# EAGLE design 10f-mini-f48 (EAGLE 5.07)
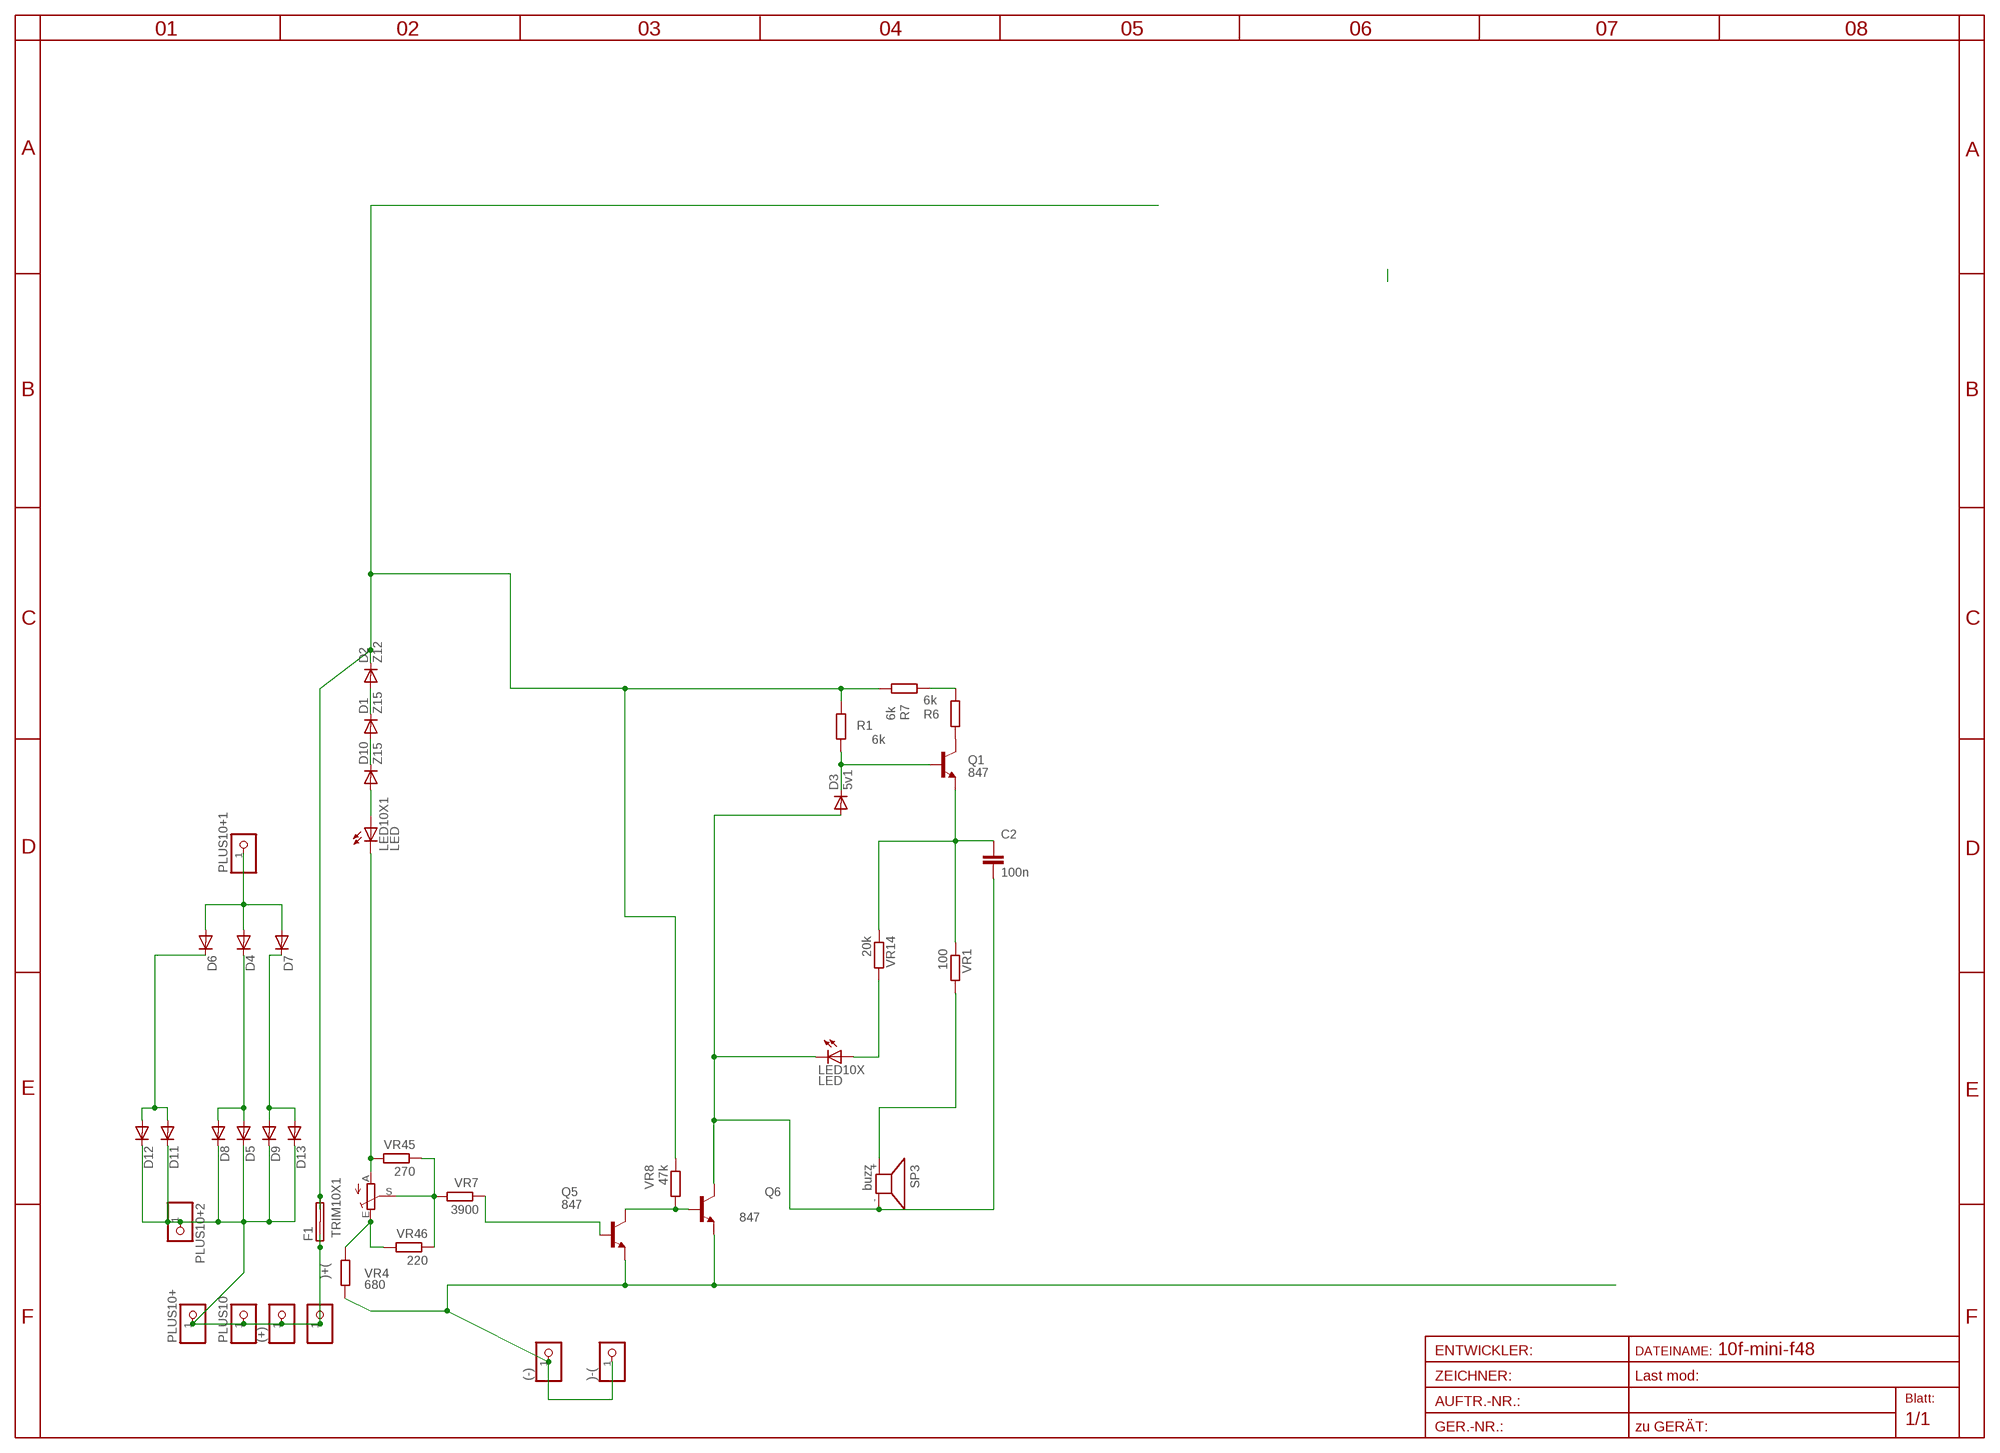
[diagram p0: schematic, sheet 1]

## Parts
(+)  PINHD-1X14.5MM  [1X4MM5]
(-)  PINHD-1X14.5MM  [1X4MM5]
)+(  PINHD-1X11X0.4  [1X01]
)-(  PINHD-1X11X0.4  [1X01]
C2  100n  C-EUC1206  [C1206]
D1  Z15  DIODE-MINIMELF  [MINIMELF]
D2  Z12  DIODE-MINIMELF  [MINIMELF]
D3  5v1  DIODE-MINIMELF  [MINIMELF]
D4  DIODE-SMC  [SMC]
D5  DIODE-SMC  [SMC]
D6  DIODE-SMC  [SMC]
D7  DIODE-SMC  [SMC]
D8  DIODE-SMC  [SMC]
D9  DIODE-SMC  [SMC]
D10  Z15  DIODE-MINIMELF  [MINIMELF]
D11  DIODE-SMC  [SMC]
D12  DIODE-SMC  [SMC]
D13  DIODE-SMC  [SMC]
F1  SHK20L7MM5  [7MM5]
LED10X  LED  LEDCHIPLED_1206  [CHIPLED_1206]
LED10X1  LED  LEDCHIPLED_1206  [CHIPLED_1206]
PLUS10  PINHD-1X14.5MM  [1X4MM5]
PLUS10+  PINHD-1X11X0.4  [1X01]
PLUS10+1  PINHD-1X11X0.4  [1X01]
PLUS10+2  PINHD-1X11X0.4  [1X01]
Q1  847  BC847CSMD  [SOT23]
Q5  847  BC847CSMD  [SOT23]
Q6  847  BC847CSMD  [SOT23]
R1  6k  R-EU_R1206  [R1206]
R6  6k  R-EU_R1206  [R1206]
R7  6k  R-EU_R1206  [R1206]
SP3  buzz  KSS12017MM  [KSS1202]
TRIM10X1  TRIM_EU-S64W  [S64W]
VR1  100  R-EU_R0805  [R0805]
VR4  680  R-EU_R0805  [R0805]
VR7  3900  R-EU_R1206  [R1206]
VR8  47k  R-EU_R1206  [R1206]
VR14  20k  R-EU_R0805  [R0805]
VR45  270  R-EU_R0805  [R0805]
VR46  220  R-EU_R1206  [R1206]

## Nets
BUZZ+: SP3.+ VR1.2
FPLUS: D2.C F1.2A F1.2B R1.2 R7.1 VR8.1
INPLUS: (+).1 )+(.1 D5.C D8.C D9.C D11.C D12.C D13.C F1.1A F1.1B PLUS10+2.1 PLUS10+.1 PLUS10.1
LEDA: LED10X.A VR14.2
N$1: D1.C D2.A
N$2: D3.C Q1.1(B) R1.1
N$3: Q5.3(C) Q6.1(B) VR8.2
N$4: D1.A D10.C
N$5: C2.2 D3.A LED10X.C Q6.3(C) SP3.-
N$6: Q1.3(C) R6.2
N$7: D4.C D5.A D8.A
N$8: C2.1 Q1.2(E) VR1.1 VR14.1
N$9: D4.A D6.A D7.A PLUS10+1.1
N$10: D10.A LED10X1.A
N$11: D7.C D9.A D13.A
N$12: D6.C D11.A D12.A
N$17: LED10X1.C TRIM10X1.A VR45.2
N$18: R6.1 R7.2
N$22: TRIM10X1.S VR7.2 VR45.1 VR46.1
N$24: TRIM10X1.E VR4.1 VR46.2
N$168: Q5.1(B) VR7.1
VSS: (-).1 )-(.1 Q5.2(E) Q6.2(E) VR4.2

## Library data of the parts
(+) (-) )+( )-( PLUS10 PLUS10+ PLUS10+1 PLUS10+2 = pinhead:PINHD-1X1: PIN HEADER
C2 = rcl:C-EU: CAPACITOR, European symbol
D1-D13 = diode:DIODE-: DIODE
F1 = fuse:SHK20L: FUSE HOLDER 5 x 20 mm, SH contact, SHH1 Schukat, E1073 Buerklin
LED10X LED10X1 = led:LED: LED
Q1 Q5 Q6 = transistor-npn:BC847*: NPN Transistor
R1 R6 R7 VR1 VR4 VR7 VR8 VR14 VR45 VR46 = rcl-2:R-EU_: RESISTOR, European symbol
SP3 = buzzer:KSS1201: SPEAKER
TRIM10X1 = pot:TRIM_EU-: POTENTIOMETER

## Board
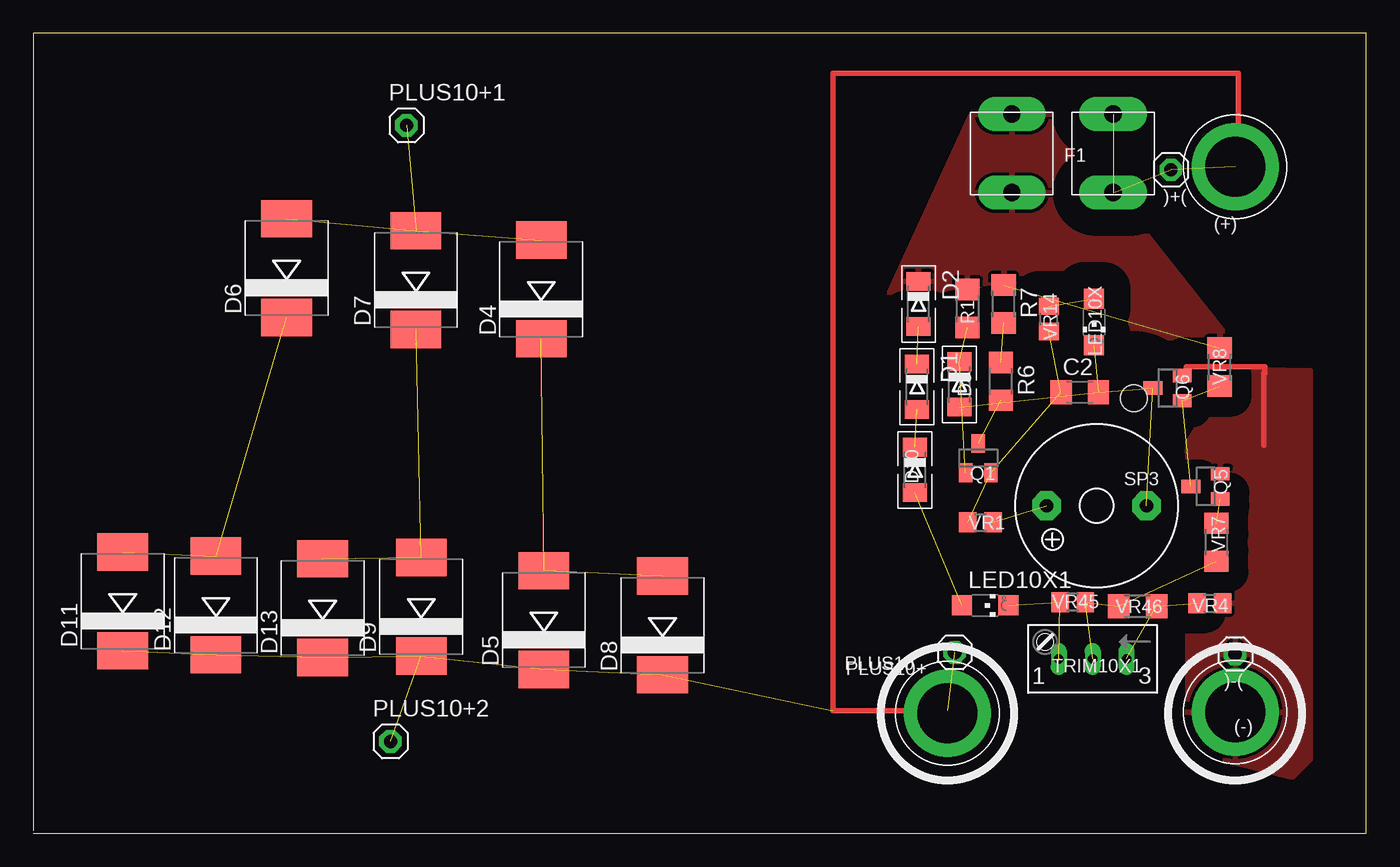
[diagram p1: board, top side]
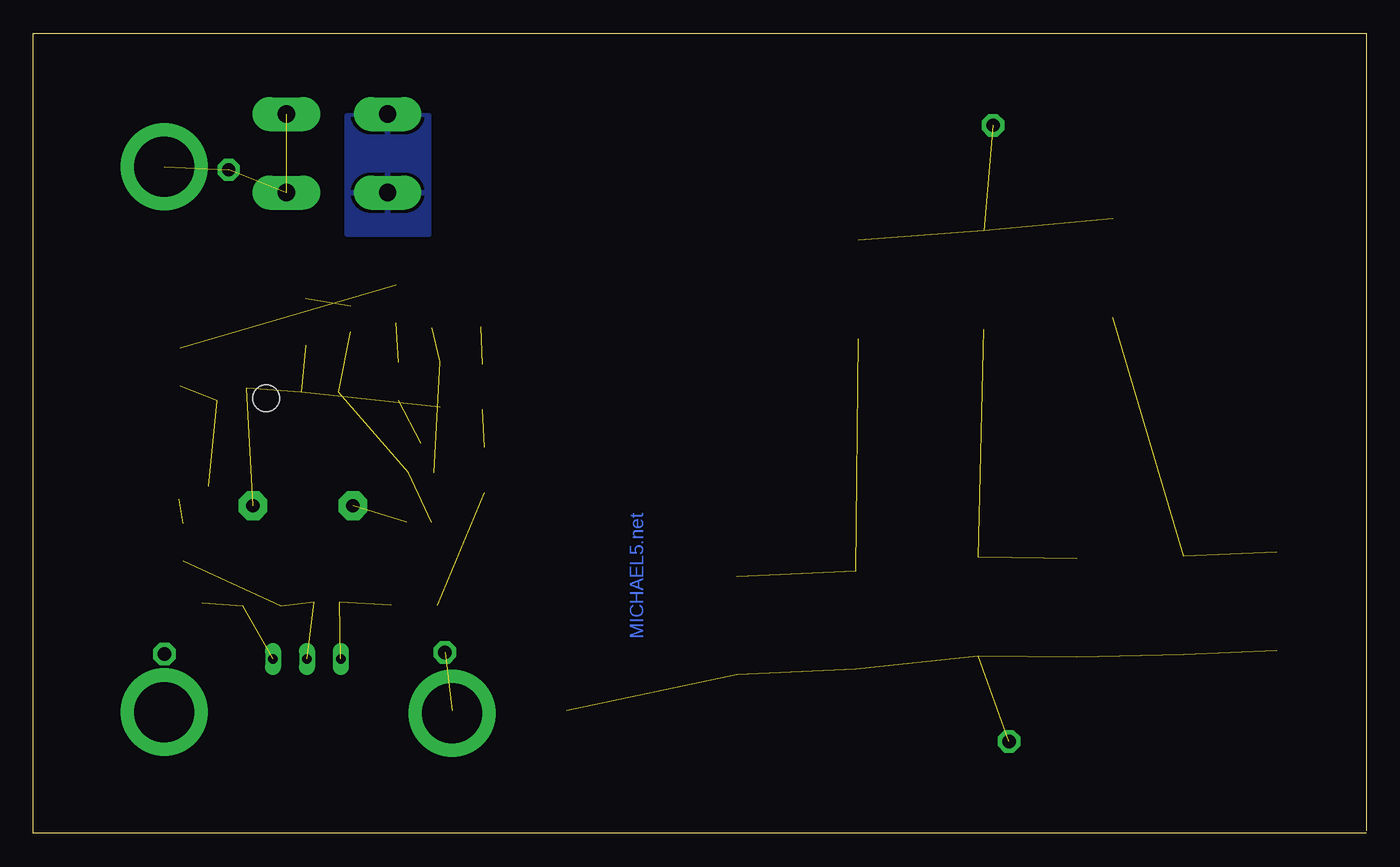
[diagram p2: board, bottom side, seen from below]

Size 100 x 60 mm. Coordinates in mm from the lower left corner, seen from the top.
Outline: 0,0 100,0 100,60 0,60 0,0.2
Copper layers (1*16): Top 0.035mm / dielectric 1.5mm / Bottom 0.035mm
Design rules "default *": minimum track width 8mil, minimum drill 4mil, track to track 8mil, track to pad 8mil, pad to pad 8mil, via to via 8mil, smd to smd 8mil, copper to edge 4mm, drill to drill 8mil, minimum pad ring 10mil, minimum via ring 8mil, stop-mask expansion 4mil, vias tented up to drill 0mil, thermal gap 10mil
Holes 2 mm at 82.55,32.64

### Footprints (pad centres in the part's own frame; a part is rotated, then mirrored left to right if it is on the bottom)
1X4MM5 = drill 4.5 pad 6.35 round: 1 0,0
1X01 = drill 1 pad 1.676 octagon: 1 0,0
C1206 = smd 1.6 x 1.8: 1 -1.4,0; 2 1.4,0
MINIMELF = smd 1.4 x 1.8: A 1.7,0; C -1.7,0
SMC = smd 2.8 x 3.8: A 3.7,0; C -3.7,0
7MM5 = drill 1.3 pad 2.54 long: 1A -3.8,2.94; 1B -3.8,-2.94; 2A 3.8,2.94; 2B 3.8,-2.94
CHIPLED_1206 = smd 1.5 x 1.5: A 0,-1.75; C 0,1.75
SOT23 = smd 1 x 1.4: 1 -0.95,-1.1; 2 0.95,-1.1; 3 0,1.1
R1206 = smd 1.6 x 1.803: 1 -1.422,0; 2 1.422,0
KSS1202 = drill 1 pad 2.159 octagon: + 3.75,0; - -3.75,0
S64W = drill 0.7 long: A 2.54,1.27; E -2.54,1.27; S 0,1.27
R0805 = smd 1.3 x 1.5: 1 -0.95,0; 2 0.95,0

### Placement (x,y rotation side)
(+)  90.17,50 0 top
(-)  90.17,9.1 0 top
)+(  85.34,49.77 0 top
)-(  90.17,13.45 0 top
C2  78.51,33.07 0 top
D1  66.3,33.5 270 top
D2  66.42,39.7 270 top
D3  69.48,33.67 270 top
D4  38.1,40.8 90 top
D5  38.3,16 90 top
D6  19,42.4 90 top
D7  28.7,41.5 90 top
D8  47.2,15.6 90 top
D9  29.1,17 90 top
D10  66.16,27.25 270 top
D11  6.7,17.4 90 top
D12  13.7,17.1 90 top
D13  21.7,16.9 90 top
F1  77.22,51 180 top
LED10X  79.59,38.34 180 top
LED10X1  71.4,17.1 270 top
PLUS10  68.58,9 0 top
PLUS10+  69.12,13.57 0 top
PLUS10+1  28,53.1 0 top
PLUS10+2  26.8,6.9 0 top
Q1  70.89,28.14 0 top
Q5  87.95,26.02 90 top
Q6  85.09,33.4 90 top
R1  70.08,39.35 90 top
R6  72.6,33.9 270 top
R7  72.8,39.7 270 top
SP3  79.77,24.57 180 top
TRIM10X1  79.47,14.35 180 top
VR1  71.06,23.31 0 top
VR4  88.27,17.26 0 top
VR7  88.77,21.83 270 top
VR8  89,34.97 270 top
VR14  76.19,38.59 90 top
VR45  77.98,17.32 180 top
VR46  82.84,17.02 0 top

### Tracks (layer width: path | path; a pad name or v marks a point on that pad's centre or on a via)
BUZZ+  (1 unrouted)
FPLUS  (1 unrouted)
  pour Top (isolate 2, rank 4): 70.36,53.83 76.45,53.83 91.15,35.24 63.56,39.04
  pour Bottom (isolate 1.5, rank 4): 70.36,53.83 76.45,53.83 76.45,44.94 70.36,44.94
INPLUS  (11 unrouted)
  Top 0.406: (+).1 90.4,50 90.4,57 60,57 60,9.2 68.58,9.2 PLUS10.1
LEDA  (1 unrouted)
N$1  (1 unrouted)
N$2  (2 unrouted)
N$3  (2 unrouted)
N$4  (1 unrouted)
N$5  (4 unrouted)
N$6  (1 unrouted)
N$7  (2 unrouted)
N$8  (3 unrouted)
N$9  (3 unrouted)
N$10  (1 unrouted)
N$11  (2 unrouted)
N$12  (2 unrouted)
N$17  (2 unrouted)
N$18  (1 unrouted)
N$22  (3 unrouted)
N$24  (2 unrouted)
N$168  (1 unrouted)
VSS
  Top 0.406: Q6.2 86.5,34.35 86.5,35 92.4,35 92.4,34.5 92.3,34.5 92.3,29.1
  pour Top (isolate 1.5, rank 2): 86.6,6.2 86.6,34.9 95.8,34.7 95.8,5.6 94.4,4.2

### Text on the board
Bottom: MICHAEL5.net
tTest: 4v4
Document: 1m | 10u | 10u | 300u | 2mA | 500u | 1m | 2m | 300u | 300u | 30u | 5m | 14m | 12m | 500u | 5m | 5m | 5m | 5m | 5m | 5m | 40m | 40m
